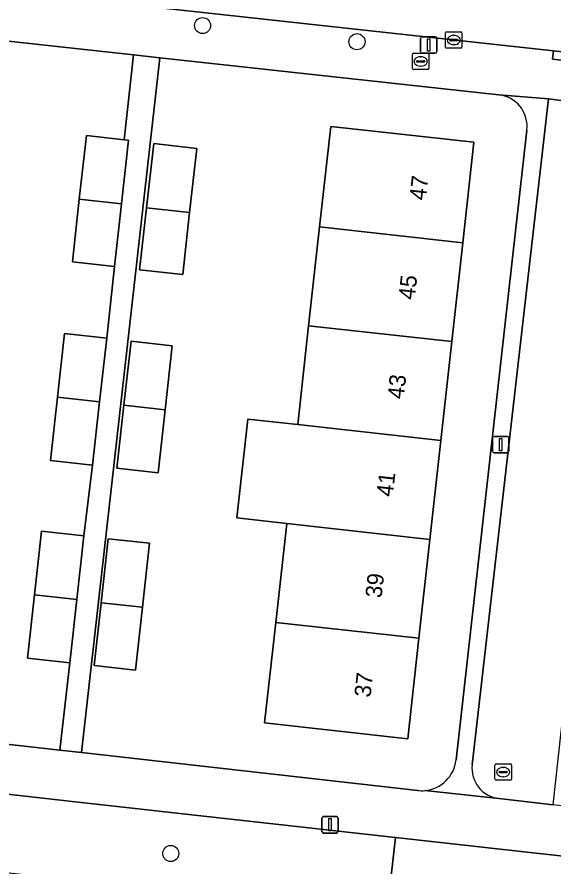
# Model space of a CAD drawing. Extents: x 161928 to 163071, y 386474 to 387428.
# Drawn here: x 162221.3 to 162253.9, y 386515.8 to 386567.4 of the extents above; entities that cross this region are included whole.
import ezdxf

# ---------------------------------------------------------------- set-up
doc = ezdxf.new("R2010")
doc.units = 0
for name, color, linetype in [('IMGEO_Boom', 7, 'Continuous'), ('IMGEO_Brandkraan', 7, 'Continuous'), ('IMGEO_Erf', 7, 'Continuous'), ('IMGEO_Gemengd_bos', 7, 'Continuous'), ('IMGEO_Kolk', 7, 'Continuous'), ('IMGEO_Lichtmast', 7, 'Continuous'), ('IMGEO_Pand', 7, 'Continuous'), ('IMGEO_Pand_nummerreeks', 7, 'Continuous'), ('IMGEO_Rijbaan_lokaal_open', 7, 'Continuous'), ('IMGEO_Rioolput', 7, 'Continuous'), ('IMGEO_Voetpad_open', 7, 'Continuous')]:
    doc.layers.add(name, color=color, linetype=linetype)

msp = doc.modelspace()

# ---------------------------------------------------------------- linework, layer by layer
at = {"layer": 'IMGEO_Boom'}
for centre in [(162232.585, 386566.912), (162241.975, 386565.93), (162230.651, 386516.569)]:
    msp.add_circle(centre, 0.489, dxfattribs=at)
at = {"layer": 'IMGEO_Brandkraan'}
for p, q in [((162245.35, 386564.305), (162245.35, 386565.157)), ((162245.425, 386565.231), (162246.277, 386565.231)), ((162246.351, 386565.157), (162246.351, 386564.305)), ((162245.609, 386564.725), (162245.609, 386564.737)), ((162246.047, 386564.688), (162245.649, 386564.688)), ((162245.652, 386564.774), (162246.05, 386564.774)), ((162245.838, 386565.011), (162245.863, 386565.011)), ((162246.093, 386564.737), (162246.093, 386564.725)), ((162246.277, 386564.231), (162245.425, 386564.231)), ((162245.861, 386564.451), (162245.836, 386564.451))]:
    msp.add_line(p, q, dxfattribs=at)
for points in [[(162245.35, 386564.305), (162245.35, 386565.157)], [(162245.425, 386565.231), (162246.277, 386565.231)], [(162246.351, 386565.157), (162246.351, 386564.305)], [(162246.277, 386564.231), (162245.425, 386564.231)]]:
    msp.add_lwpolyline(points, dxfattribs=at)
for centre, radius, start, end in [((162245.427, 386565.155), 0.0765, 91.552, 178.448), ((162245.427, 386565.155), 0.0765, 91.552, 178.448), ((162246.275, 386565.155), 0.0765, 1.552, 88.448), ((162246.275, 386565.155), 0.0765, 1.552, 88.448), ((162245.649, 386564.734), 0.0403, 85.8775, 175.7526), ((162245.646, 386564.724), 0.0366, 178.938, 274.7102), ((162246.05, 386564.731), 0.043, 264.8664, 352.4533), ((162246.054, 386564.736), 0.0386, 1.7309, 96.639), ((162245.427, 386564.307), 0.0765, 181.552, 268.448), ((162245.427, 386564.307), 0.0765, 181.552, 268.448), ((162246.275, 386564.307), 0.0765, 271.552, 358.448), ((162246.275, 386564.307), 0.0765, 271.552, 358.448)]:
    msp.add_arc(centre, radius, start, end, dxfattribs=at)
for centre, major_axis, ratio, start_param, end_param in [((162245.837, 386564.731), (-0.387, 0.002), 0.722429, 4.712389, 7.853982), ((162245.862, 386564.731), (-0.39, 0.002), 0.717154, 1.570796, 4.712389)]:
    msp.add_ellipse(centre, major_axis=major_axis, ratio=ratio, start_param=start_param, end_param=end_param, dxfattribs=at)
at = {"layer": 'IMGEO_Erf'}
for points in [[(162225.896, 386540.19), (162223.328, 386540.475), (162223.755, 386544.322), (162224.185, 386548.197), (162226.753, 386547.912), (162227.231, 386552.252), (162224.663, 386552.537), (162225.087, 386556.355), (162225.516, 386560.226), (162227.822, 386559.97), (162228.384, 386565.127), (162215.553, 386566.525), (162206.218, 386567.564), (162205.437, 386560.624), (162201.776, 386525.342), (162223.909, 386522.85), (162224.507, 386528.163), (162221.939, 386528.448), (162222.366, 386532.295), (162222.796, 386536.17), (162225.364, 386535.885)], [(162249.084, 386559.815), (162248.406, 386553.708), (162247.739, 386547.695), (162247.071, 386541.682), (162246.404, 386535.668), (162245.736, 386529.655), (162245.059, 386523.551), (162236.357, 386524.517), (162237.034, 386530.621), (162237.702, 386536.634), (162234.675, 386536.97), (162235.342, 386542.984), (162238.369, 386542.648), (162239.036, 386548.661), (162239.703, 386554.674), (162240.381, 386560.781)], [(162231.376, 386551.767), (162228.758, 386552.057), (162229.176, 386555.825), (162229.61, 386559.735), (162232.228, 386559.445), (162231.794, 386555.535)], [(162229.886, 386539.714), (162227.375, 386539.993), (162227.8, 386543.821), (162228.232, 386547.711), (162230.743, 386547.432), (162230.311, 386543.542)], [(162228.924, 386531.54), (162228.499, 386527.712), (162225.988, 386527.991), (162226.413, 386531.819), (162226.845, 386535.709), (162229.356, 386535.43)]]:
    msp.add_lwpolyline(points, close=True, dxfattribs=at)
for points in [[(162250.594, 386562.706), (162229.979, 386564.953), (162225.221, 386522.702), (162245.671, 386520.399)], [(162248, 386522.259), (162252.312, 386560.551)]]:
    msp.add_lwpolyline(points, dxfattribs=at)
for centre, radius, start, end in [((162250.378, 386560.772), 1.946, 353.4939, 83.631), ((162245.904, 386522.494), 2.109, 275.4948, 353.5904), ((162245.908, 386522.541), 2.155, 263.6807, 275.2656)]:
    msp.add_arc(centre, radius, start, end, dxfattribs=at)
at = {"layer": 'IMGEO_Gemengd_bos'}
for points in [[(162244.314, 386517.547), (162224.653, 386519.735), (162210.364, 386521.35), (162203.272, 386522.117), (162212.87, 386516.261), (162224.131, 386515.029), (162243.789, 386512.877)], [(162256.748, 386511.459), (162259.637, 386510.771), (162272.737, 386509.296), (162273.275, 386514.324), (162244.314, 386517.547), (162243.789, 386512.877)]]:
    msp.add_lwpolyline(points, close=True, dxfattribs=at)
at = {"layer": 'IMGEO_Kolk'}
for p, q in [((162247.36, 386565.607), (162247.36, 386566.459)), ((162247.435, 386566.533), (162248.287, 386566.533)), ((162247.848, 386566.313), (162247.873, 386566.313)), ((162248.361, 386566.459), (162248.361, 386565.607)), ((162247.619, 386566.027), (162247.619, 386566.039)), ((162248.057, 386565.99), (162247.659, 386565.99)), ((162247.662, 386566.076), (162248.06, 386566.076)), ((162247.871, 386565.753), (162247.846, 386565.753)), ((162248.103, 386566.039), (162248.103, 386566.027)), ((162248.287, 386565.533), (162247.435, 386565.533))]:
    msp.add_line(p, q, dxfattribs=at)
for points in [[(162247.36, 386565.607), (162247.36, 386566.459)], [(162247.435, 386566.533), (162248.287, 386566.533)], [(162248.361, 386566.459), (162248.361, 386565.607)], [(162248.287, 386565.533), (162247.435, 386565.533)]]:
    msp.add_lwpolyline(points, dxfattribs=at)
for centre, radius, start, end in [((162247.437, 386566.457), 0.0765, 91.552, 178.448), ((162247.437, 386566.457), 0.0765, 91.552, 178.448), ((162248.285, 386566.457), 0.0765, 1.552, 88.448), ((162248.285, 386566.457), 0.0765, 1.552, 88.448), ((162247.437, 386565.609), 0.0765, 181.552, 268.448), ((162247.437, 386565.609), 0.0765, 181.552, 268.448), ((162247.659, 386566.036), 0.0403, 85.8775, 175.7526), ((162247.656, 386566.026), 0.0366, 178.938, 274.7102), ((162248.06, 386566.033), 0.043, 264.8664, 352.4533), ((162248.064, 386566.038), 0.0386, 1.7309, 96.639), ((162248.285, 386565.609), 0.0765, 271.552, 358.448), ((162248.285, 386565.609), 0.0765, 271.552, 358.448)]:
    msp.add_arc(centre, radius, start, end, dxfattribs=at)
for centre, major_axis, ratio, start_param, end_param in [((162247.847, 386566.033), (-0.387, 0.002), 0.722429, 4.712389, 7.853982), ((162247.872, 386566.033), (-0.39, 0.002), 0.717154, 1.570796, 4.712389)]:
    msp.add_ellipse(centre, major_axis=major_axis, ratio=ratio, start_param=start_param, end_param=end_param, dxfattribs=at)
at = {"layer": 'IMGEO_Lichtmast'}
for p, q in [((162245.843, 386565.332), (162245.843, 386566.132)), ((162245.843, 386566.132), (162245.843, 386565.332)), ((162245.943, 386566.232), (162246.733, 386566.232)), ((162246.733, 386566.232), (162245.943, 386566.232)), ((162246.833, 386566.132), (162246.833, 386565.332)), ((162246.833, 386565.332), (162246.833, 386566.132)), ((162246.733, 386565.232), (162245.943, 386565.232)), ((162245.943, 386565.232), (162246.733, 386565.232)), ((162250.225, 386541.032), (162250.225, 386541.832)), ((162250.225, 386541.832), (162250.225, 386541.032)), ((162250.325, 386541.932), (162251.115, 386541.932)), ((162251.115, 386541.932), (162250.325, 386541.932)), ((162251.215, 386541.832), (162251.215, 386541.032)), ((162251.215, 386541.032), (162251.215, 386541.832)), ((162251.115, 386540.932), (162250.325, 386540.932)), ((162250.325, 386540.932), (162251.115, 386540.932)), ((162239.84, 386517.914), (162239.84, 386518.714)), ((162239.84, 386518.714), (162239.84, 386517.914)), ((162239.94, 386518.814), (162240.73, 386518.814)), ((162240.73, 386518.814), (162239.94, 386518.814)), ((162240.83, 386518.714), (162240.83, 386517.914)), ((162240.83, 386517.914), (162240.83, 386518.714)), ((162240.73, 386517.814), (162239.94, 386517.814)), ((162239.94, 386517.814), (162240.73, 386517.814))]:
    msp.add_line(p, q, dxfattribs=at)
for points in [[(162246.263, 386566.107), (162246.413, 386566.107), (162246.413, 386565.357), (162246.263, 386565.357), (162246.263, 386566.107)], [(162250.645, 386541.807), (162250.795, 386541.807), (162250.795, 386541.057), (162250.645, 386541.057), (162250.645, 386541.807)], [(162240.26, 386518.689), (162240.41, 386518.689), (162240.41, 386517.939), (162240.26, 386517.939), (162240.26, 386518.689)]]:
    msp.add_lwpolyline(points, dxfattribs=at)
for centre, start, end in [((162245.943, 386566.132), 90, 180), ((162245.943, 386566.132), 90, 180), ((162246.733, 386566.132), 0, 90), ((162246.733, 386566.132), 360, 90), ((162245.943, 386565.332), 180, 270), ((162245.943, 386565.332), 180, 270), ((162246.733, 386565.332), 270, 0), ((162246.733, 386565.332), 270, 0), ((162250.325, 386541.832), 90, 180), ((162250.325, 386541.832), 90, 180), ((162251.115, 386541.832), 0, 90), ((162251.115, 386541.832), 360, 90), ((162250.325, 386541.032), 180, 270), ((162250.325, 386541.032), 180, 270), ((162251.115, 386541.032), 270, 0), ((162251.115, 386541.032), 270, 0), ((162239.94, 386518.714), 90, 180), ((162239.94, 386518.714), 90, 180), ((162240.73, 386518.714), 0, 90), ((162240.73, 386518.714), 360, 90), ((162239.94, 386517.914), 180, 270), ((162239.94, 386517.914), 180, 270), ((162240.73, 386517.914), 270, 0), ((162240.73, 386517.914), 270, 0)]:
    msp.add_arc(centre, 0.1, start, end, dxfattribs=at)
at = {"layer": 'IMGEO_Pand'}
for points in [[(162248.406, 386553.708), (162249.084, 386559.815), (162240.381, 386560.781), (162239.703, 386554.674)], [(162228.084, 386559.941), (162227.822, 386559.97), (162225.516, 386560.226), (162225.087, 386556.355), (162227.655, 386556.075)], [(162231.794, 386555.535), (162232.228, 386559.445), (162229.61, 386559.735), (162229.176, 386555.825)], [(162225.087, 386556.355), (162224.663, 386552.537), (162227.231, 386552.252), (162227.655, 386556.075)], [(162229.176, 386555.825), (162228.758, 386552.057), (162231.376, 386551.767), (162231.794, 386555.535)], [(162247.739, 386547.695), (162248.406, 386553.708), (162239.703, 386554.674), (162239.036, 386548.661)], [(162239.036, 386548.661), (162238.369, 386542.648), (162247.071, 386541.682), (162247.739, 386547.695)], [(162226.753, 386547.912), (162224.185, 386548.197), (162223.755, 386544.322), (162226.323, 386544.042)], [(162230.743, 386547.432), (162228.232, 386547.711), (162227.8, 386543.821), (162230.311, 386543.542)], [(162223.328, 386540.475), (162225.896, 386540.19), (162226.323, 386544.042), (162223.755, 386544.322)], [(162227.375, 386539.993), (162229.886, 386539.714), (162230.311, 386543.542), (162227.8, 386543.821)], [(162247.071, 386541.682), (162238.369, 386542.648), (162235.342, 386542.984), (162234.675, 386536.97), (162237.702, 386536.634), (162246.404, 386535.668)], [(162224.934, 386532.015), (162225.364, 386535.885), (162222.796, 386536.17), (162222.366, 386532.295)], [(162245.736, 386529.655), (162246.404, 386535.668), (162237.702, 386536.634), (162237.034, 386530.621)], [(162228.924, 386531.54), (162229.356, 386535.43), (162226.845, 386535.709), (162226.413, 386531.819)], [(162222.366, 386532.295), (162221.939, 386528.448), (162224.507, 386528.163), (162224.934, 386532.015)], [(162226.413, 386531.819), (162225.988, 386527.991), (162228.499, 386527.712), (162228.924, 386531.54)], [(162237.034, 386530.621), (162236.357, 386524.517), (162245.059, 386523.551), (162245.736, 386529.655)]]:
    msp.add_lwpolyline(points, close=True, dxfattribs=at)
at = {"layer": 'IMGEO_Rijbaan_lokaal_open'}
msp.add_lwpolyline([(162253.921, 386565.373), (162259.408, 386564.757), (162261.164, 386564.56), (162261.912, 386571.45), (162256.384, 386572.068), (162250.613, 386572.714), (162244.143, 386573.437), (162208.921, 386577.363), (162207.377, 386577.546), (162206.668, 386570.539), (162216.075, 386569.522)], close=True, dxfattribs=at)
msp.add_lwpolyline([(162250.604, 386519.914), (162253.913, 386519.523), (162255.205, 386531.372), (162257.805, 386555.216), (162258.523, 386561.805), (162253.622, 386562.454), (162248.98, 386521.964)], dxfattribs=at)
msp.add_arc((162250.823, 386521.755), 1.854, 173.5405, 263.2317, dxfattribs=at)
at = {"layer": 'IMGEO_Rioolput'}
for p, q in [((162250.37, 386521.093), (162250.37, 386521.945)), ((162250.445, 386522.019), (162251.297, 386522.019)), ((162250.858, 386521.799), (162250.883, 386521.799)), ((162251.371, 386521.945), (162251.371, 386521.093)), ((162250.629, 386521.513), (162250.629, 386521.525)), ((162251.067, 386521.476), (162250.669, 386521.476)), ((162250.672, 386521.562), (162251.07, 386521.562)), ((162250.881, 386521.239), (162250.856, 386521.239)), ((162251.113, 386521.525), (162251.113, 386521.513)), ((162251.297, 386521.019), (162250.445, 386521.019))]:
    msp.add_line(p, q, dxfattribs=at)
for points in [[(162250.37, 386521.093), (162250.37, 386521.945)], [(162250.445, 386522.019), (162251.297, 386522.019)], [(162251.371, 386521.945), (162251.371, 386521.093)], [(162251.297, 386521.019), (162250.445, 386521.019)]]:
    msp.add_lwpolyline(points, dxfattribs=at)
for centre, radius, start, end in [((162250.447, 386521.943), 0.0765, 91.552, 178.448), ((162250.447, 386521.943), 0.0765, 91.552, 178.448), ((162251.295, 386521.943), 0.0765, 1.552, 88.448), ((162251.295, 386521.943), 0.0765, 1.552, 88.448), ((162250.669, 386521.522), 0.0403, 85.8775, 175.7526), ((162250.666, 386521.512), 0.0366, 178.938, 274.7102), ((162251.07, 386521.519), 0.043, 264.8664, 352.4533), ((162251.074, 386521.524), 0.0386, 1.7309, 96.639), ((162250.447, 386521.095), 0.0765, 181.552, 268.448), ((162250.447, 386521.095), 0.0765, 181.552, 268.448), ((162251.295, 386521.095), 0.0765, 271.552, 358.448), ((162251.295, 386521.095), 0.0765, 271.552, 358.448)]:
    msp.add_arc(centre, radius, start, end, dxfattribs=at)
for centre, major_axis, ratio, start_param, end_param in [((162250.857, 386521.519), (-0.387, 0.002), 0.722429, 4.712389, 7.853982), ((162250.882, 386521.519), (-0.39, 0.002), 0.717154, 1.570796, 4.712389)]:
    msp.add_ellipse(centre, major_axis=major_axis, ratio=ratio, start_param=start_param, end_param=end_param, dxfattribs=at)
at = {"layer": 'IMGEO_Voetpad_open'}
for points in [[(162264.757, 386564.157), (162261.164, 386564.56), (162259.408, 386564.757), (162259.352, 386564.248), (162253.864, 386564.861), (162253.921, 386565.373), (162216.075, 386569.522), (162206.668, 386570.539), (162206.218, 386567.564), (162215.553, 386566.525), (162228.384, 386565.127), (162229.979, 386564.953), (162250.594, 386562.706), (162253.622, 386562.454), (162258.523, 386561.805), (162261.299, 386561.458)], [(162253.622, 386562.454), (162250.594, 386562.706)], [(162248.98, 386521.964), (162253.622, 386562.454)], [(162252.312, 386560.551), (162248, 386522.259)], [(162245.671, 386520.399), (162225.221, 386522.702), (162223.909, 386522.85), (162201.776, 386525.342), (162202.401, 386522.176), (162203.272, 386522.117), (162210.364, 386521.35), (162224.653, 386519.735), (162244.314, 386517.547), (162273.275, 386514.324), (162298.087, 386511.519), (162347.162, 386505.951), (162371.516, 386503.188), (162382.205, 386501.975), (162382.604, 386505.469), (162378.144, 386505.94), (162375.565, 386506.213), (162368.502, 386506.62), (162368.281, 386506.633), (162347.875, 386508.944), (162346.386, 386509.112), (162326.011, 386511.421)], [(162264.858, 386518.27), (162260.434, 386518.756), (162259.937, 386518.81), (162253.913, 386519.523), (162250.604, 386519.914), (162246.106, 386520.395)], [(162246.106, 386520.395), (162250.604, 386519.914)]]:
    msp.add_lwpolyline(points, dxfattribs=at)
for points in [[(162229.979, 386564.953), (162228.384, 386565.127), (162227.822, 386559.97), (162228.084, 386559.941), (162227.655, 386556.075), (162227.231, 386552.252), (162226.753, 386547.912), (162226.323, 386544.042), (162225.896, 386540.19), (162225.364, 386535.885), (162224.934, 386532.015), (162224.507, 386528.163), (162223.909, 386522.85), (162225.221, 386522.702)], [(162259.408, 386564.757), (162253.921, 386565.373), (162253.864, 386564.861), (162259.352, 386564.248)]]:
    msp.add_lwpolyline(points, close=True, dxfattribs=at)
for centre, radius, start, end in [((162250.378, 386560.772), 1.946, 353.4939, 83.631), ((162245.904, 386522.494), 2.109, 275.4948, 353.5904), ((162250.823, 386521.755), 1.854, 173.5405, 263.2317), ((162245.908, 386522.541), 2.155, 263.6807, 275.2656)]:
    msp.add_arc(centre, radius, start, end, dxfattribs=at)

# ---------------------------------------------------------------- texts
at = {"layer": 'IMGEO_Pand_nummerreeks'}
for s, rotation, p in [('47', 83.6666, (162246.153, 386556.25)), ('45', 83.6666, (162245.482, 386550.206)), ('43', 83.6666, (162244.812, 386544.162)), ('41', 83.669, (162244.153, 386538.23)), ('39', 83.6666, (162243.47, 386532.074)), ('37', 83.6666, (162242.799, 386526.03))]:
    msp.add_text(s, height=1, rotation=rotation, dxfattribs=at).set_placement(p)

doc.saveas('drawing.dxf')
